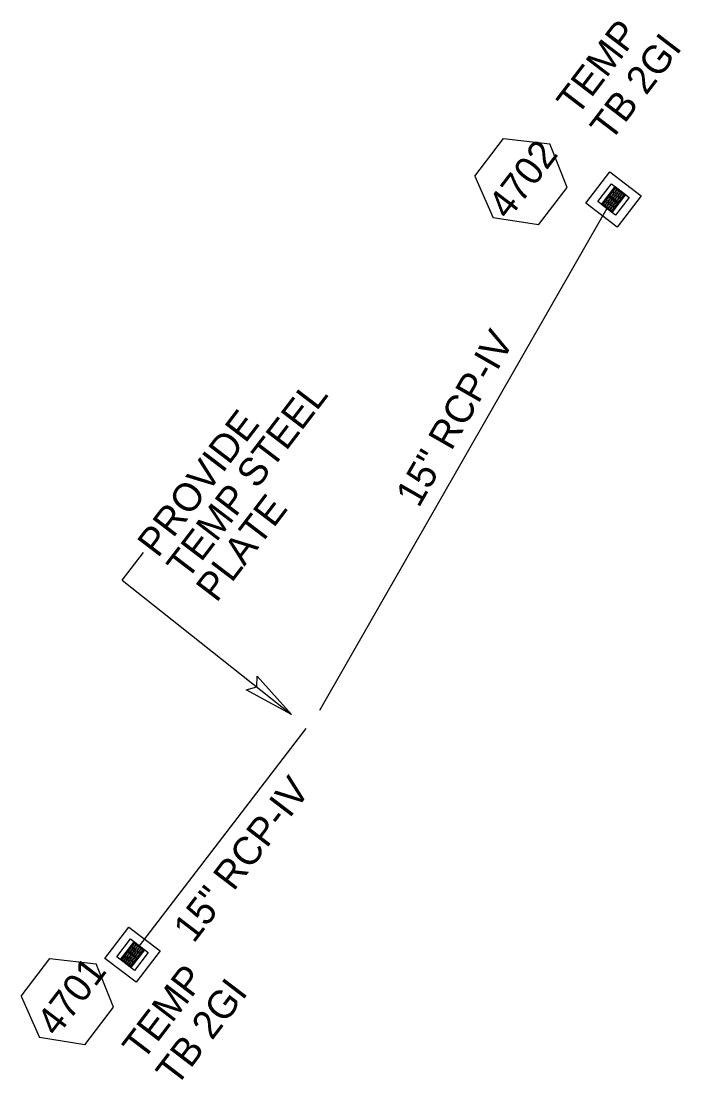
# Model space of a CAD drawing. Extents: x 2214419 to 2238519, y 983271 to 1015868.
# Drawn here: x 2226964.2 to 2227081.4, y 997430.3 to 997618.6 of the extents above; entities that cross this region are included whole.
import ezdxf

# ---------------------------------------------------------------- set-up
doc = ezdxf.new("R2010")
doc.units = 0
for name, color, linetype in [('Prop Drainage Structure Box Number Symbol CELL', 7, 'Continuous'), ('Prop Drainage Structure Drop Inlet Grate 2 Wide Slots and Sag Grates 840 22 TB CELL', 7, 'Continuous'), ('Prop Drainage Structure Drop Inlet Grate 2 Wide Slots and Sag Grates 840 22 TB Label', 7, 'Continuous'), ('Prop Drainage Structure Pipe RCP 15in Class IV', 7, 'Continuous'), ('Prop Drainage Structure Pipe RCP 15in Class IV Label', 7, 'Continuous'), ('Prop Drainage Structure Plot Symbol 20 Scale', 7, 'Continuous'), ('Prop Drainage Structure Plot Symbol 50 Scale', 7, 'Continuous'), ('Prop Plan Preparation Drainage Notes Label', 7, 'Continuous')]:
    doc.layers.add(name, color=color, linetype=linetype)

msp = doc.modelspace()

# ---------------------------------------------------------------- linework, layer by layer
at = {"layer": 'Prop Drainage Structure Box Number Symbol CELL'}
for p, q in [((2227044.82, 997591.03), (2227049.92, 997597.7)), ((2227049.92, 997597.7), (2227058.18, 997596.76)), ((2227061.26, 997589.03), (2227058.18, 997596.76)), ((2227044.82, 997591.03), (2227048.06, 997583.63)), ((2227056.16, 997582.36), (2227061.26, 997589.03)), ((2227056.16, 997582.36), (2227048.06, 997583.63)), ((2226964.17, 997445.25), (2226969.27, 997451.93)), ((2226969.27, 997451.93), (2226977.53, 997450.98)), ((2226980.61, 997443.26), (2226977.53, 997450.98)), ((2226964.17, 997445.25), (2226967.41, 997437.85)), ((2226975.51, 997436.58), (2226980.61, 997443.26)), ((2226975.51, 997436.58), (2226967.41, 997437.85))]:
    msp.add_line(p, q, dxfattribs=at)
at = {"layer": 'Prop Drainage Structure Drop Inlet Grate 2 Wide Slots and Sag Grates 840 22 TB CELL'}
for p, q in [((2227068.55, 997587.59), (2227068.55, 997587.59)), ((2227070.69, 997588.47), (2227070.69, 997588.47)), ((2227068.26, 997585.29), (2227068.26, 997585.29)), ((2227069.48, 997586.88), (2227069.48, 997586.88)), ((2227070.4, 997586.17), (2227070.4, 997586.17)), ((2226983.03, 997453.32), (2226983.03, 997453.32)), ((2226985.17, 997454.2), (2226985.17, 997454.2)), ((2226983.96, 997452.61), (2226983.96, 997452.61)), ((2226984.89, 997451.9), (2226984.89, 997451.9)), ((2226982.74, 997451.02), (2226982.74, 997451.02))]:
    msp.add_line(p, q, dxfattribs=at)
for points in [[(2227071.62, 997587.76), (2227069.19, 997584.58), (2227067.34, 997586), (2227069.76, 997589.18), (2227071.62, 997587.76)], [(2227071.53, 997587.75), (2227069.18, 997584.67), (2227067.42, 997586.01), (2227069.78, 997589.09), (2227071.53, 997587.75), (2227071.53, 997587.75)], [(2227071.52, 997587.75), (2227070.35, 997586.22), (2227068.61, 997587.55), (2227069.78, 997589.08), (2227071.52, 997587.75)], [(2227070.09, 997588.73), (2227069.59, 997588.07), (2227069.37, 997588.23), (2227069.88, 997588.9), (2227070.09, 997588.73)], [(2227070.34, 997586.21), (2227069.18, 997584.69), (2227067.44, 997586.01), (2227068.6, 997587.54), (2227070.34, 997586.21)], [(2227068.91, 997587.19), (2227068.41, 997586.53), (2227068.19, 997586.69), (2227068.7, 997587.36), (2227068.91, 997587.19)], [(2227069.22, 997586.96), (2227068.72, 997586.3), (2227068.5, 997586.46), (2227069.01, 997587.12), (2227069.22, 997586.96)], [(2227069.53, 997588), (2227069.03, 997587.34), (2227068.81, 997587.51), (2227069.32, 997588.17), (2227069.53, 997588)], [(2227069.84, 997587.77), (2227069.34, 997587.11), (2227069.12, 997587.27), (2227069.63, 997587.93), (2227069.84, 997587.77)], [(2227070.15, 997587.53), (2227069.64, 997586.87), (2227069.43, 997587.04), (2227069.93, 997587.7), (2227070.15, 997587.53)], [(2227070.4, 997588.5), (2227069.89, 997587.84), (2227069.68, 997588), (2227070.18, 997588.66), (2227070.4, 997588.5)], [(2227070.45, 997587.3), (2227069.95, 997586.64), (2227069.73, 997586.8), (2227070.24, 997587.47), (2227070.45, 997587.3)], [(2227070.7, 997588.26), (2227070.2, 997587.6), (2227069.98, 997587.77), (2227070.49, 997588.43), (2227070.7, 997588.26)], [(2227070.76, 997587.07), (2227070.25, 997586.4), (2227070.04, 997586.57), (2227070.54, 997587.23), (2227070.76, 997587.07)], [(2227071.01, 997588.03), (2227070.5, 997587.37), (2227070.29, 997587.53), (2227070.8, 997588.19), (2227071.01, 997588.03)], [(2227071.32, 997587.8), (2227070.81, 997587.13), (2227070.6, 997587.3), (2227071.1, 997587.96), (2227071.32, 997587.8)], [(2227068.36, 997586.46), (2227067.85, 997585.8), (2227067.64, 997585.97), (2227068.14, 997586.63), (2227068.36, 997586.46)], [(2227068.66, 997586.23), (2227068.16, 997585.57), (2227067.94, 997585.73), (2227068.45, 997586.39), (2227068.66, 997586.23)], [(2227068.97, 997586), (2227068.46, 997585.33), (2227068.25, 997585.5), (2227068.76, 997586.16), (2227068.97, 997586)], [(2227069.28, 997585.76), (2227068.77, 997585.1), (2227068.56, 997585.26), (2227069.06, 997585.93), (2227069.28, 997585.76)], [(2227069.53, 997586.72), (2227069.02, 997586.06), (2227068.81, 997586.23), (2227069.31, 997586.89), (2227069.53, 997586.72)], [(2227069.58, 997585.53), (2227069.08, 997584.87), (2227068.86, 997585.03), (2227069.37, 997585.69), (2227069.58, 997585.53)], [(2227069.83, 997586.49), (2227069.33, 997585.83), (2227069.11, 997585.99), (2227069.62, 997586.65), (2227069.83, 997586.49)], [(2227070.14, 997586.26), (2227069.63, 997585.59), (2227069.42, 997585.76), (2227069.92, 997586.42), (2227070.14, 997586.26)], [(2226986.1, 997453.49), (2226983.67, 997450.31), (2226981.82, 997451.73), (2226984.25, 997454.91), (2226986.1, 997453.49)], [(2226986.01, 997453.48), (2226983.66, 997450.4), (2226981.9, 997451.74), (2226984.26, 997454.82), (2226986.01, 997453.48), (2226986.01, 997453.48)], [(2226986, 997453.48), (2226984.83, 997451.95), (2226983.1, 997453.28), (2226984.26, 997454.8), (2226986, 997453.48)], [(2226984.02, 997453.73), (2226983.51, 997453.07), (2226983.3, 997453.23), (2226983.8, 997453.9), (2226984.02, 997453.73)], [(2226984.32, 997453.5), (2226983.82, 997452.83), (2226983.6, 997453), (2226984.11, 997453.66), (2226984.32, 997453.5)], [(2226984.57, 997454.46), (2226984.07, 997453.8), (2226983.85, 997453.96), (2226984.36, 997454.62), (2226984.57, 997454.46)], [(2226984.63, 997453.26), (2226984.12, 997452.6), (2226983.91, 997452.77), (2226984.41, 997453.43), (2226984.63, 997453.26)], [(2226984.88, 997454.23), (2226984.37, 997453.56), (2226984.16, 997453.73), (2226984.66, 997454.39), (2226984.88, 997454.23)], [(2226985.19, 997453.99), (2226984.68, 997453.33), (2226984.46, 997453.49), (2226984.97, 997454.16), (2226985.19, 997453.99)], [(2226985.49, 997453.76), (2226984.99, 997453.1), (2226984.77, 997453.26), (2226985.28, 997453.92), (2226985.49, 997453.76)], [(2226985.8, 997453.52), (2226985.29, 997452.86), (2226985.08, 997453.03), (2226985.58, 997453.69), (2226985.8, 997453.52)], [(2226984.82, 997451.94), (2226983.66, 997450.41), (2226981.92, 997451.74), (2226983.08, 997453.26), (2226984.82, 997451.94)], [(2226982.84, 997452.19), (2226982.33, 997451.53), (2226982.12, 997451.69), (2226982.63, 997452.36), (2226982.84, 997452.19)], [(2226983.15, 997451.96), (2226982.64, 997451.3), (2226982.43, 997451.46), (2226982.93, 997452.12), (2226983.15, 997451.96)], [(2226983.4, 997452.92), (2226982.89, 997452.26), (2226982.68, 997452.42), (2226983.18, 997453.08), (2226983.4, 997452.92)], [(2226983.45, 997451.72), (2226982.95, 997451.06), (2226982.73, 997451.23), (2226983.24, 997451.89), (2226983.45, 997451.72)], [(2226983.7, 997452.69), (2226983.2, 997452.02), (2226982.98, 997452.19), (2226983.49, 997452.85), (2226983.7, 997452.69)], [(2226983.76, 997451.49), (2226983.25, 997450.83), (2226983.04, 997450.99), (2226983.54, 997451.65), (2226983.76, 997451.49)], [(2226984.01, 997452.45), (2226983.5, 997451.79), (2226983.29, 997451.95), (2226983.79, 997452.62), (2226984.01, 997452.45)], [(2226984.32, 997452.22), (2226983.81, 997451.56), (2226983.59, 997451.72), (2226984.1, 997452.38), (2226984.32, 997452.22)], [(2226984.62, 997451.98), (2226984.12, 997451.32), (2226983.9, 997451.49), (2226984.41, 997452.15), (2226984.62, 997451.98)], [(2226984.94, 997453.03), (2226984.43, 997452.37), (2226984.21, 997452.53), (2226984.72, 997453.19), (2226984.94, 997453.03)], [(2226985.24, 997452.79), (2226984.74, 997452.13), (2226984.52, 997452.3), (2226985.03, 997452.96), (2226985.24, 997452.79)], [(2226984.07, 997451.26), (2226983.56, 997450.59), (2226983.34, 997450.76), (2226983.85, 997451.42), (2226984.07, 997451.26)]]:
    msp.add_lwpolyline(points, dxfattribs=at)
at = {"layer": 'Prop Drainage Structure Pipe RCP 15in Class IV'}
for p, q in [((2227068.26, 997585.29), (2227017.19, 997496.02)), ((2227014.76, 997492.84), (2226985.17, 997454.2))]:
    msp.add_line(p, q, dxfattribs=at)
at = {"layer": 'Prop Drainage Structure Plot Symbol 20 Scale'}
for points in [[(2227072.28, 997587.25), (2227069.85, 997584.08), (2227066.67, 997586.51), (2227069.1, 997589.68)], [(2226986.76, 997452.98), (2226984.33, 997449.8), (2226981.16, 997452.23), (2226983.58, 997455.41)]]:
    msp.add_lwpolyline(points, close=True, dxfattribs=at)
at = {"layer": 'Prop Drainage Structure Plot Symbol 50 Scale'}
for points in [[(2227074.38, 997587.54), (2227070.13, 997581.97), (2227064.57, 997586.23), (2227068.82, 997591.79)], [(2226988.86, 997453.26), (2226984.61, 997447.7), (2226979.05, 997451.95), (2226983.3, 997457.51)]]:
    msp.add_lwpolyline(points, close=True, dxfattribs=at)
at = {"layer": 'Prop Plan Preparation Drainage Notes Label'}
for q in [(2226985.9, 997524.08), (2227012.23, 997495.3)]:
    msp.add_line((2226982.15, 997519.17), q, dxfattribs=at)
msp.add_lwpolyline([(2227006.15, 997502.11), (2227012.23, 997495.3), (2227004.15, 997499.67), (2227006.04, 997500.21)], close=True, dxfattribs=at)

# ---------------------------------------------------------------- texts
at = {"layer": 'Prop Drainage Structure Box Number Symbol CELL'}
for s, p in [('4702', (2227050.77, 997583.09)), ('4701', (2226970.51, 997437.82))]:
    msp.add_text(s, height=5, rotation=52.6073, dxfattribs=at).set_placement(p)
at = {"layer": 'Prop Drainage Structure Drop Inlet Grate 2 Wide Slots and Sag Grates 840 22 TB Label'}
for s, p in [('TEMP', (2227063, 997601.54)), ('TB 2GI', (2227068.95, 997596.99)), ('TEMP', (2226985.81, 997433.53)), ('TB 2GI', (2226991.77, 997428.97))]:
    msp.add_text(s, height=5, rotation=52.6073, dxfattribs=at).set_placement(p)
at = {"layer": 'Prop Drainage Structure Pipe RCP 15in Class IV Label'}
for rotation, p in [(60.2265, (2227034.84, 997531.9)), (52.5602, (2226994.83, 997454.47))]:
    msp.add_text('15" RCP-IV ', height=5, rotation=rotation, dxfattribs=at).set_placement(p)
at = {"layer": 'Prop Plan Preparation Drainage Notes Label'}
for s, p in [('TEMP STEEL', (2226993.67, 997519.02)), ('PROVIDE', (2226988.46, 997523)), ('PLATE', (2226998.88, 997515.05))]:
    msp.add_text(s, height=5, rotation=52.6215, dxfattribs=at).set_placement(p)

doc.saveas('drawing.dxf')
